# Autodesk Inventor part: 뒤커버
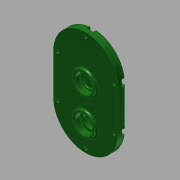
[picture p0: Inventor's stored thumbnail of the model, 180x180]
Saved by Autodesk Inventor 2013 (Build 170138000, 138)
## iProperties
Created: 2016-12
Part Number: 뒤커버
Material: 일반
Document SubType Name: Modeling
Designer: mduedu
Density: 1 g/cm^3
Author: mduedu
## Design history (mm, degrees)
sketch "스케치1"
  geometry: L1 (40, -25)-(40, 25); L2 (-40, 25)-(-40, -25); L3 (-40, -25)-(40, 25); L4 (40, -25)-(-40, 25); A1 r 40 centre (0, 25) between (40, 25) and (-40, 25); A2 r 40 centre (0, -25) between (-40, -25) and (40, -25); 1 further point
  constraints: 8 end point, 4 point on circle, 4 tangent, 2 centre point, 2 midpoint, 1 parallel, 1 vertical
  dimensions: "d0" = 130 dimension on A2 A1; "d2" = 80 distance between parallel lines of L1 L2
extrude "돌출1" new body sketch "스케치1" distance "d3" = 10; taper "d4" = 0 deg
sketch "스케치2"
  geometry: C1 r 14 at (0, 11); 1 further point
  constraints: 1 centre point, 1 vertical alignment
  dimensions: "d5" = 28 diameter of C1; "d6" = 11 distance of C1.centre point (0, 0)
extrude "돌출2" join sketch "스케치2" distance "d7" = 3; taper "d8" = 0 deg
sketch "스케치3"
  geometry: C1 r 14 at (0, -33.1); C2 r 14 at (0, 11) reference; 1 further point
  constraints: 1 centre point, 1 vertical alignment
  dimensions: "d9" = 28 diameter of C1; "d69" = 44.1 distance of C1.centre C2.centre
extrude "돌출3" join sketch "스케치3" distance "d11" = 3; taper "d12" = 0 deg
hole "구멍1" diameter "d15" = 22; stored, may be unused: countersink angle "d19" = 90 deg, drill point angle "d21" = 0 deg; dims "d13" = 10, "d14" = 10, "d16" = 6, "d17" = 4, "d18" = 2, "d20" = 7
hole "구멍2" diameter "d24" = 18; stored, may be unused: countersink angle "d28" = 90 deg, drill point angle "d30" = 0 deg; dims "d22" = 10, "d23" = 10, "d25" = 6, "d26" = 4, "d27" = 2, "d29" = 1
hole "구멍3" diameter "d33" = 22; stored, may be unused: countersink angle "d37" = 90 deg, drill point angle "d39" = 0 deg; dims "d31" = 10, "d32" = 10, "d34" = 6, "d35" = 4, "d36" = 2, "d38" = 7
sketch "스케치4"
  geometry: C1 r 14 at (0, -33.1) reference; C2 r 18 at (0, -33.1); 1 further point
  constraints: 1 centre point, 1 coincident
  dimensions: "d40" = 36 diameter of C2
extrude "돌출4" join sketch "스케치4" distance "d41" = 4; taper "d42" = 0 deg
hole "구멍4" diameter "d45" = 22; stored, may be unused: countersink angle "d49" = 90 deg, drill point angle "d51" = 0 deg; dims "d43" = 10, "d44" = 10, "d46" = 6, "d47" = 4, "d48" = 2, "d50" = 7
hole "구멍5" diameter "d54" = 15; stored, may be unused: countersink angle "d58" = 90 deg, drill point angle "d60" = 0 deg; dims "d52" = 10, "d53" = 10, "d55" = 6, "d56" = 4, "d57" = 2, "d59" = 7
fillet "모깎기1" dims "d61" = 0.3
fillet "모깎기2" dims "d62" = 2
chamfer "모따기1" distance "d63" = 1; stored, may be unused: second distance "d64" = 2, angle "d65" = 45 deg
fillet "모깎기3" dims "d66" = 2
fillet "모깎기4" dims "d67" = 2
fillet "모깎기5" dims "d68" = 2
sketch "스케치5"
  geometry: L1 (-40, 25)-(-40, -25) reference; L2 (40, -25)-(40, 25) reference; L3 (35, 25)-(35, -25); L4 (-35, -25)-(-35, 25); A1 r 40 centre (0, 25) between (40, 25) and (-40, 25) reference; A2 r 40 centre (0, -25) between (-40, -25) and (40, -25) reference; A3 r 35 centre (0, 25) between (35, 25) and (-35, 25); A4 r 35 centre (0, -25) between (-35, -25) and (35, -25); 2 further points
  constraints: 5 point on circle, 4 end point, 2 centre point, 1 vertical alignment, 3 other
  dimensions: "d70" = 5 distance between parallel lines of L2 L3
sketch "스케치6"
  geometry: 1 further point
hole "구멍6" sketch "스케치6" at (0, 60) diameter "d71" = 4.5; stored, may be unused: countersink angle "d75" = 90 deg, drill point angle "d77" = 0 deg; dims "d72" = 6, "d73" = 8, "d74" = 4.6, "d76" = 8
sketch "스케치7"
  geometry: L1 (-4, 0)-(4, 0); L2 (4, 0)-(4, 5); L3 (4, 5)-(-4, 5); L4 (-4, 5)-(-4, 0); C1 r 2.25 at (0, 0) reference; A1 r 40 centre (0, -35) between (40, -35) and (-40, -35) reference; 2 further points
  constraints: 8 end point, 2 parallel, 2 vertical, 1 horizontal, 1 horizontal alignment, 1 perpendicular, 1 tangent, 1 other
extrude "돌출5" cut sketch "스케치7" stored distance "d80" = 10; taper "d81" = 0 deg
fillet "모깎기6" dims "d82" = 0.3
fillet "모깎기7" dims "d83" = 0.3
node "솔리드1"
pattern_linear "직사각형 패턴1"
node "투영된 루프1"
